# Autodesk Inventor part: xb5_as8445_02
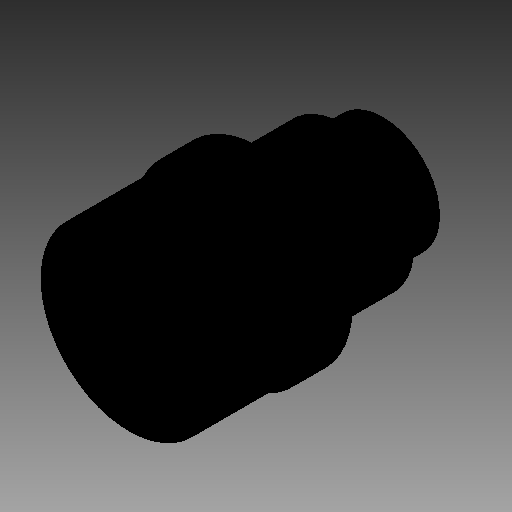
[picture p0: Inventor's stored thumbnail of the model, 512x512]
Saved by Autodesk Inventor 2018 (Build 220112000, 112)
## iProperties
Company: TraceParts S.A.
Created: 2018-04
Part Number: xb5_as8445_02
Checked By: TraceParts S.A.
Material: Generic
Catalog Web Link: www.traceparts.com
Document SubType Name: Modeling
Designer: TraceParts
Density: 1 g/cm^3
Appearance: Default
Author: TraceParts
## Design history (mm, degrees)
feature "xb5_as8445_02.ipt"
body "Solid1"
